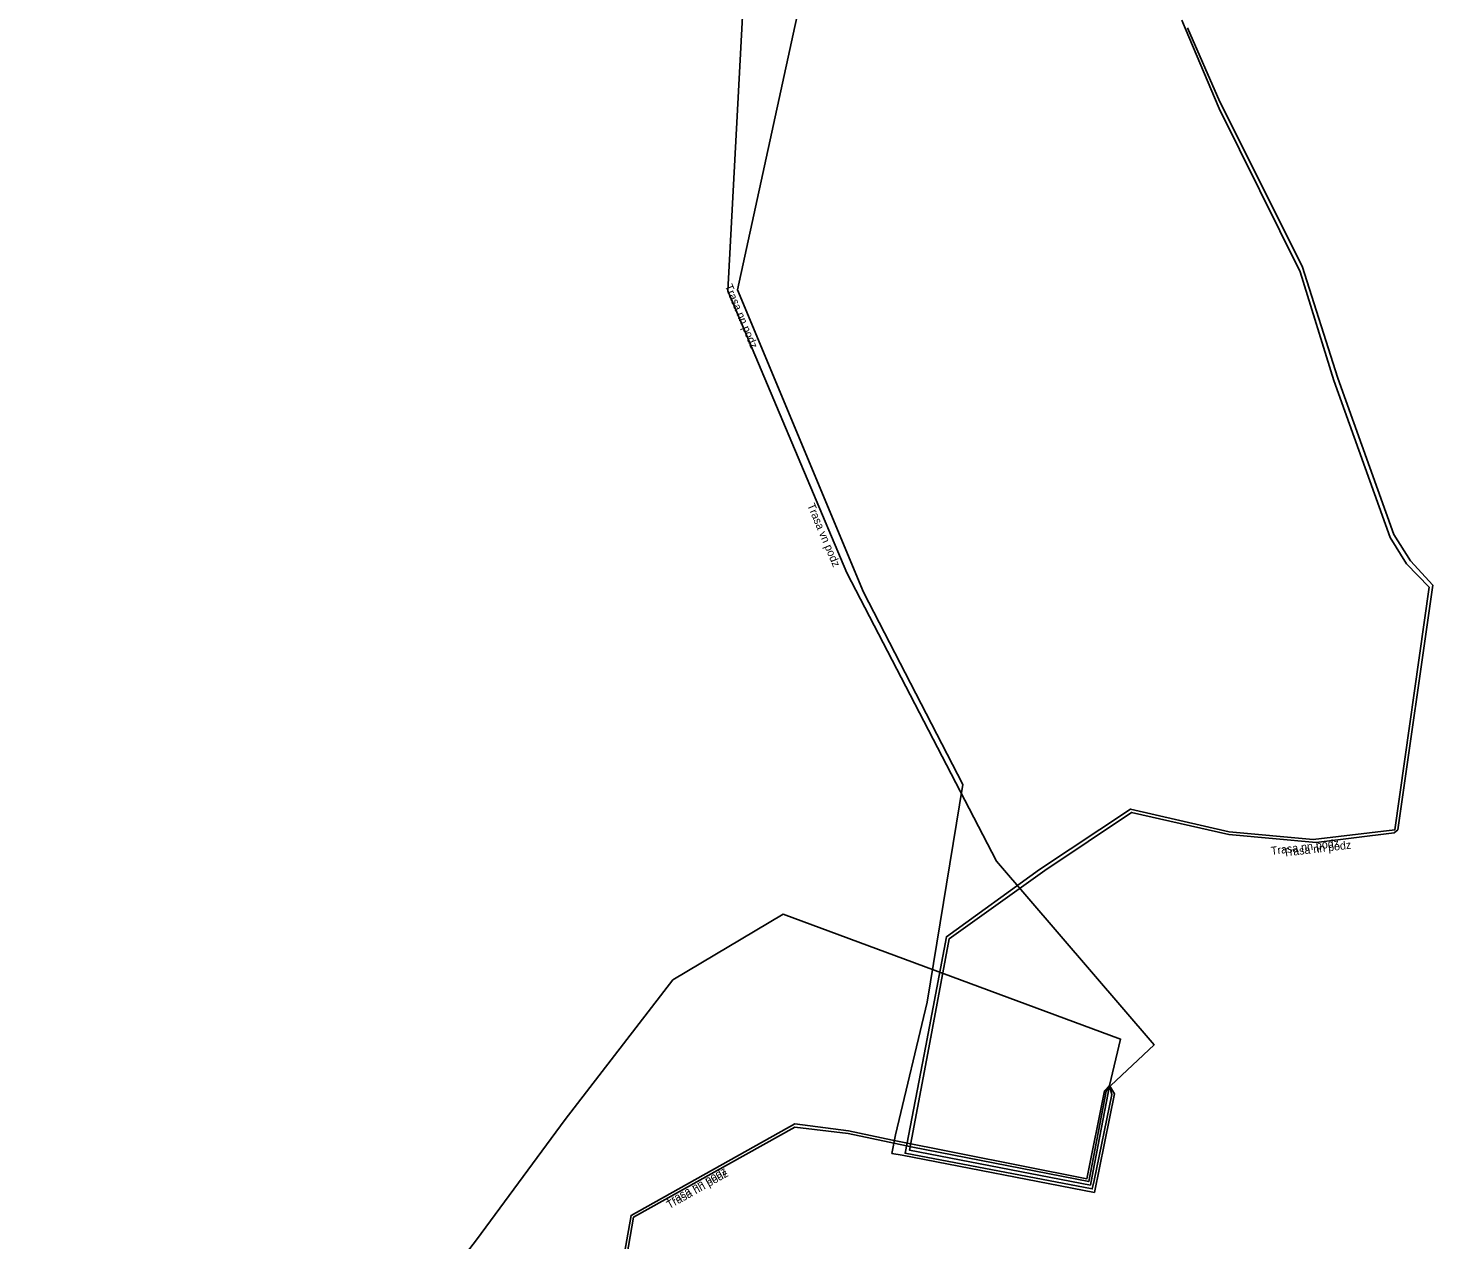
# Model space of a CAD drawing. Extents: x -875087 to -874407, y -1056142 to -1055396.
# Drawn here: x -874544 to -874456.2, y -1055889.5 to -1055813.9 of the extents above; entities that cross this region are included whole.
import ezdxf

# ---------------------------------------------------------------- set-up
doc = ezdxf.new("R2010")
doc.units = 0
for name, color, linetype in [('Popiskový text - Ostatní atributy Trasy', 7, 'Continuous'), ('Spojnice NN', 7, 'Continuous'), ('Spojnice VN', 7, 'Continuous')]:
    doc.layers.add(name, color=color, linetype=linetype)

msp = doc.modelspace()

# ---------------------------------------------------------------- linework, layer by layer
at = {"layer": 'Spojnice NN'}
for points in [[(-874476.442, -1055879.876), (-874476.123, -1055880.406), (-874477.372, -1055886.555), (-874489.374, -1055884.233), (-874490.02, -1055884.117), (-874489.806, -1055882.948), (-874487.818, -1055874.674), (-874485.599, -1055861.083), (-874491.806, -1055849.075), (-874499.666, -1055830.214), (-874495.282, -1055810.035), (-874492.855, -1055798.848), (-874490.498, -1055788.478), (-874488.735, -1055783.434), (-874478.596, -1055781.048), (-874475.337, -1055775.613), (-874474.306, -1055771.567), (-874473.798, -1055768.649)], [(-874471.924, -1055813.383), (-874471.717, -1055813.872)], [(-874471.717, -1055813.872), (-874469.594, -1055818.891), (-874464.524, -1055829.091), (-874462.424, -1055835.861), (-874458.908, -1055845.675), (-874457.875, -1055847.316), (-874456.478, -1055848.774), (-874458.604, -1055863.908), (-874463.71, -1055864.516), (-874468.96, -1055864.035), (-874475.119, -1055862.626), (-874480.816, -1055866.39), (-874486.624, -1055870.594), (-874487.9, -1055877.401), (-874489.206, -1055884.104), (-874477.507, -1055886.336), (-874477.385, -1055885.802), (-874476.292, -1055880.44), (-874476.442, -1055879.876)], [(-874471.57, -1055813.849), (-874469.534, -1055818.469), (-874464.404, -1055828.728), (-874462.171, -1055835.73), (-874458.665, -1055845.492), (-874457.632, -1055847.133), (-874456.235, -1055848.653), (-874458.422, -1055863.908), (-874458.653, -1055864.115), (-874463.528, -1055864.698), (-874468.98, -1055864.215), (-874475.059, -1055862.826), (-874480.473, -1055866.45), (-874486.441, -1055870.715), (-874487.718, -1055877.523), (-874488.933, -1055883.904), (-874477.628, -1055886.093), (-874477.456, -1055885.202), (-874476.534, -1055880.44), (-874476.442, -1055879.876)], [(-874476.442, -1055879.876), (-874476.736, -1055880.203), (-874477.848, -1055885.696), (-874489.98, -1055883.29), (-874492.735, -1055882.708), (-874496.092, -1055882.264), (-874506.31, -1055887.992), (-874508.27, -1055898.984), (-874501.334, -1055900.628), (-874505.836, -1055905.7), (-874505.726, -1055905.986), (-874505.826, -1055906.014)], [(-874476.442, -1055879.876), (-874476.636, -1055880.236), (-874477.731, -1055885.879), (-874488.718, -1055883.721), (-874492.752, -1055882.875), (-874496.092, -1055882.47), (-874506.156, -1055888.096), (-874508.013, -1055898.829), (-874502.114, -1055900.177), (-874500.856, -1055900.472), (-874505.589, -1055905.875), (-874505.826, -1055906.014)]]:
    msp.add_lwpolyline(points, dxfattribs=at)
at = {"layer": 'Spojnice VN'}
for points in [[(-874499.02, -1055806.89), (-874500.268, -1055830.266), (-874492.837, -1055847.885), (-874483.497, -1055865.879), (-874473.648, -1055877.348), (-874476.357, -1055879.881)], [(-874476.437, -1055879.881), (-874475.738, -1055876.979), (-874496.813, -1055869.192), (-874503.709, -1055873.287), (-874510.442, -1055881.994), (-874515.97, -1055889.516), (-874526.398, -1055903.078), (-874534.49, -1055913.963), (-874541.898, -1055908.264), (-874553.911, -1055924.923)]]:
    msp.add_lwpolyline(points, dxfattribs=at)

# ---------------------------------------------------------------- texts
at = {"layer": 'Popiskový text - Ostatní atributy Trasy'}
for s, rotation, p in [('Trasa nn podz', 292.62143, (-874500.471, -1055829.972)), ('Trasa vn podz', 292.86545, (-874495.326, -1055843.657)), ('Trasa nn podz', 6.78812, (-874466.322, -1055865.481)), ('Trasa nn podz', 6.82505, (-874465.559, -1055865.596)), ('Trasa nn podz', 29.27849, (-874504.009, -1055887.447)), ('Trasa nn podz', 29.2069, (-874503.927, -1055887.595))]:
    msp.add_text(s, height=0.5, rotation=rotation, dxfattribs=at).set_placement(p)

doc.saveas('drawing.dxf')
